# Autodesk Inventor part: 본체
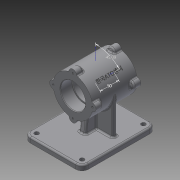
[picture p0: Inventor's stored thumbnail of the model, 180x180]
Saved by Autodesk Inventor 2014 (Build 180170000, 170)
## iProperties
Created: 2015-12
Part Number: 본체
Material: 일반
Document SubType Name: Modeling
Designer: L6
Density: 1 g/cm^3
Appearance: 기본값
Mass: 429.852 g
Surface Area: 814.673 cm^2
Volume: 429.852 cm^3
Author: L6
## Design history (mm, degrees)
sketch "스케치1"
  geometry: L1 (-42.5, 37)-(42.5, 37); L2 (42.5, 37)-(42.5, 0); L3 (42.5, 0)-(-42.5, 0); L4 (-42.5, 0)-(-42.5, 37); L5 (-42.5, 23.5)-(-20.5, 23.5); L6 (-20.5, 23.5)-(-20.5, 21); L7 (-20.5, 21)-(20.5, 21); L8 (20.5, 21)-(20.5, 23.5); L9 (20.5, 23.5)-(42.5, 23.5); 2 further points
  constraints: 18 end point, 4 parallel, 4 perpendicular, 2 collinear, 2 point on line, 1 coincident, 1 horizontal, 1 midpoint
  dimensions: "d0" = 85 distance of L1.start L1.end; "d1" = 37 distance of L3.end L1.start; "d2" = 23.5 distance between parallel lines of L3 L5; "d3" = 21 distance between parallel lines of L3 L7; "d4" = 22 distance of L5.start L5.end
revolve "회전1" sketch "스케치1" stored, may be unused: angle "d5" = 90 deg
sketch "스케치3"
  geometry: L1 (-42.5, 37)-(42.5, 37) reference; L2 (-42.5, 37)-(-27.5, 37); L3 (-42.5, 37)-(-42.5, 44); L4 (-42.5, 44)-(-30.048, 44); L5 (-27.5, 37)-(-30.048, 44); 1 further point
  constraints: 8 end point, 2 perpendicular, 1 point on line
  dimensions: "d6" = 15 distance of L1.start L2.end; "d7" = 7 distance of L1.start L3.end; "d8" = 110 deg angle of L1 L5
revolve "회전2" sketch "스케치3" stored, may be unused: angle "d9" = 90 deg
hole "구멍1" diameter "d15" = 3.242; stored, may be unused: countersink angle "d19" = 90 deg, drill point angle "d21" = 118 deg; dims "d13" = 10, "d14" = 10, "d16" = 9, "d17" = 4, "d18" = 2, "d20" = 10
hole "구멍2" diameter "d24" = 3.242; stored, may be unused: countersink angle "d28" = 90 deg, drill point angle "d30" = 118 deg; dims "d22" = 10, "d23" = 10, "d25" = 9, "d26" = 4, "d27" = 2, "d29" = 10
hole "구멍3" diameter "d33" = 3.242; stored, may be unused: countersink angle "d37" = 90 deg, drill point angle "d39" = 118 deg; dims "d31" = 10, "d32" = 10, "d34" = 9, "d35" = 4, "d36" = 2, "d38" = 10
hole "구멍4" diameter "d42" = 3.242; stored, may be unused: countersink angle "d46" = 90 deg, drill point angle "d48" = 118 deg; dims "d40" = 10, "d41" = 10, "d43" = 9, "d44" = 4, "d45" = 2, "d47" = 10
node "작업 평면1"
sketch "스케치5"
  geometry: L1 (-55, 60)-(55, 60); L2 (55, 60)-(55, -80); L3 (55, -80)-(-55, -80); L4 (-55, -80)-(-55, 60); 1 further point
  constraints: 8 end point, 2 parallel, 1 horizontal, 1 perpendicular
  dimensions: "d50" = 110 distance of L1.start L1.end; "d51" = 140 distance of L3.end L1.start; "d52" = 80 distance from line of point (0, 0) L3; "d53" = 55 distance from line of point (0, 0) L4
extrude "돌출1" join sketch "스케치5" distance "d54" = 10; taper "d55" = 0 deg
fillet "모깎기1" dims "d56" = 12
hole "구멍5" diameter "d59" = 8; stored, may be unused: countersink angle "d63" = 90 deg, drill point angle "d65" = 118 deg; dims "d57" = 10, "d58" = 10, "d60" = 9, "d61" = 4, "d62" = 2, "d64" = 10
hole "구멍6" diameter "d68" = 8; stored, may be unused: countersink angle "d72" = 90 deg, drill point angle "d74" = 118 deg; dims "d66" = 10, "d67" = 10, "d69" = 9, "d70" = 4, "d71" = 2, "d73" = 10
hole "구멍7" diameter "d77" = 8; stored, may be unused: countersink angle "d81" = 90 deg, drill point angle "d83" = 118 deg; dims "d75" = 10, "d76" = 10, "d78" = 9, "d79" = 4, "d80" = 2, "d82" = 10
hole "구멍8" diameter "d86" = 8; stored, may be unused: countersink angle "d90" = 90 deg, drill point angle "d92" = 118 deg; dims "d84" = 10, "d85" = 10, "d87" = 9, "d88" = 4, "d89" = 2, "d91" = 10
sketch "스케치6"
  geometry: L1 (43, -70)-(55, -70) reference; L2 (39, -70)-(47, -70) reference; L3 (-43, -70)-(43, -70) reference; L4 (-47, -70)-(-39, -70) reference; L5 (37, 0)-(37, -70); L6 (-37, 0)-(-37, -70); A1 r 37 centre (0, 0) between (6.969, -36.338) and (36.338, -6.969) reference; A2 r 7 centre (37, 0) between (36.338, -6.969) and (36.338, 6.969) reference; A3 r 37 centre (0, 0) between (-36.338, -6.969) and (-6.969, -36.338) reference; A4 r 7 centre (-37, 0) between (-36.338, 6.969) and (-36.338, -6.969) reference; A5 r 37 centre (0, 0) between (-37, 0) and (37, 0); 1 further point
  constraints: 4 end point, 2 perpendicular, 2 point on circle, 2 point on line, 1 centre point, 1 coincident, 2 other
extrude "돌출2" join sketch "스케치6" stored distance "d93" = 8; taper "d94" = 0 deg
sketch "스케치7"
  geometry: L1 (-27.5, -37)-(27.5, -37) reference; L2 (48, -70)-(-68, -70) reference; L3 (-25, -70)-(-20.948, -37); 1 further point
  constraints: 2 end point, 2 point on line
  dimensions: "d95" = 25 horizontal distance of L3.start point (0, 0); "d96" = 97 deg angle of L2 L3
feature "리브1" sketch "스케치7" dims "d97" = 1, "d98" = 12, "d99" = 0, "d100" = 0, "d101" = 1, "d102" = 1
sketch "스케치8"
  geometry: L1 (0, 0)-(0, 59.369); L2 (0, 0)-(-35.355, 35.355)
  constraints: 4 end point, 1 vertical
  dimensions: "d103" = 50 distance of L1.start L2.end; "d104" = 45 deg angle of L2 L1
node "작업 평면2"
sketch "스케치9"
  geometry: 2 further points
  constraints: 1 coincident, 1 other
feature "엠보싱1" sketch "스케치9" dims "d0" = 85, "d1" = 37, "d2" = 23.5, "d3" = 21, "d4" = 22, "d105" = 0.5, "d106" = 0
chamfer "모따기1" distance "d107" = 1; stored, may be unused: second distance "d108" = 2, angle "d109" = 45 deg
fillet "모깎기2" dims "d110" = 0.3
fillet "모깎기3" dims "d111" = 3
fillet "모깎기5" dims "d113" = 3
node "솔리드1"
pattern_circular "원형 패턴1" dims angle "d11" = 360 deg
mirror "대칭1"
mirror "대칭2"
pattern_circular "원형 패턴2" dims angle "d117" = 360 deg
mirror "대칭3"
